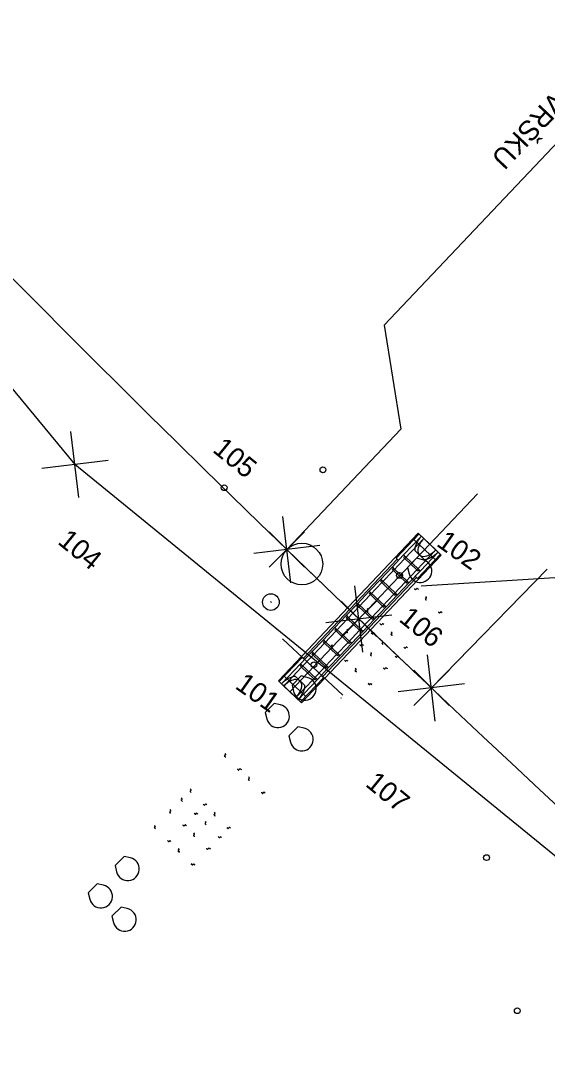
# Model space of a CAD drawing. Extents: x -505028 to -503155, y -1080361 to -1077947.
# Drawn here: x -504027.8 to -503996.3, y -1079378.2 to -1079315.9 of the extents above; entities that cross this region are included whole.
import ezdxf

# ---------------------------------------------------------------- set-up
doc = ezdxf.new("R2010")
doc.units = 0
for name, color, linetype in [('12_vytyceni', 7, 'Continuous'), ('bublinySOPS', 7, 'Continuous'), ('C3D-BOD', 7, 'Continuous'), ('C3D_Povrch - Popis', 7, 'Continuous'), ('C3D_Trasa-Popisy trasy', 7, 'Continuous'), ('Default', 7, 'Continuous'), ('Návěst místo trati_1', 7, 'Continuous'), ('SO021701 popisky', 7, 'Continuous'), ('SO02_tlustá plná', 7, 'Continuous'), ('SO02_tlustá čárkovaná', 7, 'Continuous'), ('SO02_čerchovaná', 7, 'Continuous'), ('Trasa-Geometrie', 7, 'Continuous'), ('Vrstva 17', 7, 'Continuous'), ('Vrstva 24', 7, 'Continuous'), ('Vrstva 7', 7, 'Continuous'), ('ŽKN stavba druh', 7, 'Continuous')]:
    doc.layers.add(name, color=color, linetype=linetype)

# ---------------------------------------------------------------- blocks, each defined once
blk = doc.blocks.new('C045')
at = {"layer": 'ŽKN stavba druh'}
blk.add_circle((0.01, 0), 1.75, dxfattribs=at)
blk = doc.blocks.new('_U7')
at = {"layer": 'Default'}
for p, q in [((8.82, 33.01), (8.6, 33.8)), ((9.85, 32.88), (8.96, 32.9)), ((38.34, 33.8), (38.41, 33.04)), ((46, 33.14), (46, 33.8)), ((46.86, 32.97), (46.14, 32.99)), ((47, 31.9), (47, 32.82)), ((55.82, 33.01), (55.6, 33.8)), ((56.85, 32.88), (55.96, 32.9)), ((69.14, 32.99), (69.86, 32.97)), ((69.86, 32.97), (69.14, 32.99)), ((160.36, 33.01), (160.14, 33.8)), ((161.39, 32.88), (160.5, 32.9)), ((189.88, 33.8), (189.94, 33.04)), ((197.54, 33.14), (197.54, 33.8)), ((198.39, 32.97), (197.68, 32.99)), ((198.54, 31.9), (198.54, 32.82)), ((207.36, 33.01), (207.14, 33.8)), ((208.39, 32.88), (207.5, 32.9)), ((220.68, 32.99), (221.39, 32.97)), ((221.39, 32.97), (220.68, 32.99)), ((8.82, 20.79), (8.6, 20)), ((9.85, 20.92), (8.96, 20.9)), ((38.34, 20), (38.41, 20.76)), ((46, 20.66), (46, 20)), ((46.86, 20.83), (46.14, 20.81)), ((47, 21.9), (47, 20.98)), ((55.82, 20.79), (55.6, 20)), ((56.85, 20.92), (55.96, 20.9)), ((69.14, 20.81), (69.86, 20.83)), ((69.86, 20.83), (69.14, 20.81)), ((125.77, 20), (127.79, 23.3)), ((160.36, 20.79), (160.14, 20)), ((161.39, 20.92), (160.5, 20.9)), ((189.88, 20), (189.94, 20.76)), ((197.54, 20.66), (197.54, 20)), ((198.39, 20.83), (197.68, 20.81)), ((198.54, 21.9), (198.54, 20.98)), ((207.36, 20.79), (207.14, 20)), ((208.39, 20.92), (207.5, 20.9)), ((220.68, 20.81), (221.39, 20.83)), ((221.39, 20.83), (220.68, 20.81)), ((277.31, 20), (279.32, 23.3)), ((8.82, 13.01), (8.6, 13.8)), ((9.85, 12.88), (8.96, 12.9)), ((46, 13.14), (46, 13.8)), ((46.86, 12.97), (46.14, 12.99)), ((47, 11.9), (47, 12.82)), ((55.82, 13.01), (55.6, 13.8)), ((56.85, 12.88), (55.96, 12.9)), ((69.14, 12.99), (69.86, 12.97)), ((69.86, 12.97), (69.14, 12.99)), ((160.36, 13.01), (160.14, 13.8)), ((161.39, 12.88), (160.5, 12.9)), ((197.54, 13.14), (197.54, 13.8)), ((198.39, 12.97), (197.68, 12.99)), ((198.54, 11.9), (198.54, 12.82)), ((207.36, 13.01), (207.14, 13.8)), ((208.39, 12.88), (207.5, 12.9)), ((220.68, 12.99), (221.39, 12.97)), ((221.39, 12.97), (220.68, 12.99)), ((-15.62, 6.63), (-0.12, 6.9)), ((-15.62, 6.63), (-15.58, 4.73)), ((-0.12, 6.9), (9.88, 7.07)), ((9.88, 7.07), (19.88, 7.25)), ((19.88, 7.25), (29.88, 7.42)), ((20.1, -5.6), (19.89, 6.3)), ((29.88, 7.42), (39.87, 7.6)), ((30.1, -5.43), (29.89, 6.47)), ((39.87, 7.6), (49.87, 7.77)), ((40.1, -5.25), (39.89, 6.65)), ((49.87, 7.77), (59.87, 7.95)), ((50.1, -5.08), (49.89, 6.82)), ((59.87, 7.95), (69.87, 8.12)), ((60.09, -4.9), (59.89, 7)), ((60.9, 6.06), (70.9, 6.24)), ((69.87, 8.12), (79.87, 8.3)), ((70.09, -4.73), (69.89, 7.17)), ((70.9, 6.24), (80.9, 6.41)), ((71.08, -3.76), (70.9, 6.24)), ((79.87, 8.3), (89.87, 8.47)), ((80.1, -4.84), (79.88, 7.35)), ((80.9, 6.41), (90.9, 6.59)), ((81.07, -3.59), (80.9, 6.41)), ((89.87, 8.47), (106.36, 8.76)), ((90.09, -4.38), (89.88, 7.52)), ((90.9, 6.59), (106.4, 6.86)), ((91.07, -3.41), (90.9, 6.59)), ((106.4, 6.86), (106.36, 8.76)), ((106.57, -3.14), (106.4, 6.86)), ((-15.58, 4.73), (0.91, 5.02)), ((-15.41, -5.27), (-15.58, 4.73)), ((-6.57, 3.78), (-6.43, -4.01)), ((-1, 0), (-1, 0)), ((-1, 0), (-1, 0)), ((0.1, -5.95), (-0.1, 5.95)), ((-0.02, 1), (-0.02, 1)), ((-0.02, 1), (-0.02, 1)), ((-0.02, 1), (-0.02, 1)), ((-0.02, 1), (-0.02, 1)), ((-0.02, 1), (-0.02, 1)), ((-0.02, 1), (-0.02, 1)), ((-0.02, 1), (-0.02, 1)), ((0.91, 5.02), (10.91, 5.19)), ((1.09, -4.98), (0.91, 5.02)), ((1, 0), (1, 0)), ((1, 0), (1, 0)), ((3.87, 0), (5.89, 3.3)), ((3.87, 0), (5.89, 3.3)), ((8.82, 0.79), (8.6, 0)), ((9.85, 0.92), (8.96, 0.9)), ((10.1, -5.77), (9.89, 6.12)), ((10.91, 5.19), (20.91, 5.37)), ((11.09, -4.81), (10.91, 5.19)), ((20.91, 5.37), (30.91, 5.54)), ((21.08, -4.63), (20.91, 5.37)), ((30.91, 5.54), (40.91, 5.71)), ((31.08, -4.46), (30.91, 5.54)), ((40.91, 5.71), (50.9, 5.89)), ((41.08, -4.28), (40.91, 5.71)), ((46, 0.66), (46, 0)), ((46.86, 0.83), (46.14, 0.81)), ((47, 1.9), (47, 0.98)), ((50.9, 5.89), (60.9, 6.06)), ((51.08, -4.11), (50.9, 5.89)), ((55.82, 0.79), (55.6, 0)), ((56.85, 0.92), (55.96, 0.9)), ((61.08, -3.93), (60.9, 6.06)), ((69.14, 0.81), (69.86, 0.83)), ((69.86, 0.83), (69.14, 0.81)), ((97.42, 5.59), (97.55, -2.19)), ((102.77, 0), (104.79, 3.3)), ((125.77, 0), (127.79, 3.3)), ((160.36, 0.79), (160.14, 0)), ((161.39, 0.92), (160.5, 0.9)), ((197.54, 0.66), (197.54, 0)), ((198.39, 0.83), (197.68, 0.81)), ((198.54, 1.9), (198.54, 0.98)), ((207.36, 0.79), (207.14, 0)), ((208.39, 0.92), (207.5, 0.9)), ((220.68, 0.81), (221.39, 0.83)), ((221.39, 0.83), (220.68, 0.81)), ((254.31, 0), (256.32, 3.3)), ((277.31, 0), (279.32, 3.3)), ((-15.41, -5.27), (1.09, -4.98)), ((-15.38, -7.17), (-15.41, -5.27)), ((1.09, -4.98), (11.09, -4.81)), ((11.09, -4.81), (21.08, -4.63)), ((21.08, -4.63), (31.08, -4.46)), ((30.12, -6.38), (40.11, -6.2)), ((31.08, -4.46), (41.08, -4.28)), ((40.11, -6.2), (50.11, -6.03)), ((41.08, -4.28), (51.08, -4.11)), ((50.11, -6.03), (60.11, -5.85)), ((51.08, -4.11), (61.08, -3.93)), ((60.11, -5.85), (70.11, -5.68)), ((61.08, -3.93), (71.08, -3.76)), ((70.11, -5.68), (80.11, -5.5)), ((71.08, -3.76), (81.07, -3.59)), ((80.11, -5.5), (90.11, -5.33)), ((81.07, -3.59), (91.07, -3.41)), ((90.11, -5.33), (106.6, -5.04)), ((91.07, -3.41), (106.57, -3.14)), ((106.6, -5.04), (106.57, -3.14)), ((-15.38, -7.17), (0.12, -6.9)), ((0.12, -6.9), (10.12, -6.72)), ((10.12, -6.72), (20.12, -6.55)), ((20.12, -6.55), (30.12, -6.38))]:
    blk.add_line(p, q, dxfattribs=at)
for points in [[(9.9, 31.9), (10, 32), (10, 32.73)], [(38.55, 32.9), (39.3, 32.88), (39.39, 32.85)], [(39.5, 32.71), (39.5, 32), (39.4, 31.9)], [(56.9, 31.9), (57, 32), (57, 32.73)], [(69, 33.14), (69, 33.8), (69, 33.14)], [(70, 32.82), (70, 31.9), (70, 32.82)], [(161.44, 31.9), (161.54, 32), (161.54, 32.73)], [(190.09, 32.9), (190.84, 32.88), (190.92, 32.85)], [(191.04, 32.71), (191.04, 32), (190.94, 31.9)], [(208.44, 31.9), (208.54, 32), (208.54, 32.73)], [(220.54, 33.14), (220.54, 33.8), (220.54, 33.14)], [(221.54, 32.82), (221.54, 31.9), (221.54, 32.82)], [(9.9, 21.9), (10, 21.8), (10, 21.07)], [(38.55, 20.9), (39.3, 20.92), (39.39, 20.95)], [(39.5, 21.09), (39.5, 21.8), (39.4, 21.9)], [(56.9, 21.9), (57, 21.8), (57, 21.07)], [(69, 20.66), (69, 20), (69, 20.66)], [(70, 20.98), (70, 21.9), (70, 20.98)], [(116.01, 23.3), (118.03, 20), (125.77, 20)], [(161.44, 21.9), (161.54, 21.8), (161.54, 21.07)], [(190.09, 20.9), (190.84, 20.92), (190.92, 20.95)], [(191.04, 21.09), (191.04, 21.8), (190.94, 21.9)], [(208.44, 21.9), (208.54, 21.8), (208.54, 21.07)], [(220.54, 20.66), (220.54, 20), (220.54, 20.66)], [(221.54, 20.98), (221.54, 21.9), (221.54, 20.98)], [(267.55, 23.3), (269.57, 20), (277.31, 20)], [(9.9, 11.9), (10, 12), (10, 12.73)], [(38.34, 13.8), (38.34, 13.8), (38.41, 13.04)], [(38.55, 12.9), (39.3, 12.88), (39.39, 12.85)], [(39.5, 12.71), (39.5, 12), (39.4, 11.9)], [(56.9, 11.9), (57, 12), (57, 12.73)], [(69, 13.14), (69, 13.8), (69, 13.14)], [(70, 12.82), (70, 11.9), (70, 12.82)], [(161.44, 11.9), (161.54, 12), (161.54, 12.73)], [(189.88, 13.8), (189.88, 13.8), (189.94, 13.04)], [(190.09, 12.9), (190.84, 12.88), (190.92, 12.85)], [(191.04, 12.71), (191.04, 12), (190.94, 11.9)], [(208.44, 11.9), (208.54, 12), (208.54, 12.73)], [(220.54, 13.14), (220.54, 13.8), (220.54, 13.14)], [(221.54, 12.82), (221.54, 11.9), (221.54, 12.82)], [(0.91, 5.02), (0.9, 5.97), (-0.1, 5.95), (-0.12, 6.9)], [(10.91, 5.19), (10.89, 6.14), (9.89, 6.12), (9.88, 7.07)], [(20.91, 5.37), (20.89, 6.32), (19.89, 6.3), (19.88, 7.25)], [(30.91, 5.54), (30.89, 6.49), (29.89, 6.47), (29.88, 7.42)], [(40.91, 5.71), (40.89, 6.66), (39.89, 6.65), (39.87, 7.6)], [(50.9, 5.89), (50.89, 6.84), (49.89, 6.82), (49.87, 7.77)], [(60.9, 6.06), (60.89, 7.01), (59.89, 7), (59.87, 7.95)], [(70.9, 6.24), (70.89, 7.19), (69.89, 7.17), (69.87, 8.12)], [(80.9, 6.41), (80.88, 7.36), (79.88, 7.35), (79.87, 8.3)], [(90.9, 6.59), (90.88, 7.54), (89.88, 7.52), (89.87, 8.47)], [(-5.89, 3.3), (-3.87, 0), (3.87, 0)], [(-5.89, 3.3), (-3.87, 0), (3.87, 0)], [(-1, 0), (-1, 0), (-1, 0)], [(-1, 0), (-1, 0), (-1, 0)], [(1, 0), (1, 0), (1, 0)], [(1, 0), (1, 0), (1, 0)], [(9.9, 1.9), (10, 1.8), (10, 1.07)], [(38.34, 0), (38.34, 0), (38.41, 0.76)], [(38.55, 0.9), (39.3, 0.92), (39.39, 0.95)], [(39.5, 1.09), (39.5, 1.8), (39.4, 1.9)], [(56.9, 1.9), (57, 1.8), (57, 1.07)], [(69, 0.66), (69, 0), (69, 0.66)], [(70, 0.98), (70, 1.9), (70, 0.98)], [(93.01, 3.3), (95.03, 0), (102.77, 0)], [(116.01, 3.3), (118.03, 0), (125.77, 0)], [(161.44, 1.9), (161.54, 1.8), (161.54, 1.07)], [(189.88, 0), (189.88, 0), (189.94, 0.76)], [(190.09, 0.9), (190.84, 0.92), (190.92, 0.95)], [(191.04, 1.09), (191.04, 1.8), (190.94, 1.9)], [(208.44, 1.9), (208.54, 1.8), (208.54, 1.07)], [(220.54, 0.66), (220.54, 0), (220.54, 0.66)], [(221.54, 0.98), (221.54, 1.9), (221.54, 0.98)], [(244.55, 3.3), (246.57, 0), (254.31, 0)], [(267.55, 3.3), (269.57, 0), (277.31, 0)], [(1.09, -4.98), (1.1, -5.93), (0.1, -5.95), (0.12, -6.9)], [(11.09, -4.81), (11.1, -5.76), (10.1, -5.77), (10.12, -6.72)], [(21.08, -4.63), (21.1, -5.58), (20.1, -5.6), (20.12, -6.55)], [(31.08, -4.46), (31.1, -5.41), (30.1, -5.43), (30.12, -6.38)], [(41.08, -4.28), (41.09, -5.23), (40.1, -5.25), (40.11, -6.2)], [(51.08, -4.11), (51.09, -5.06), (50.1, -5.08), (50.11, -6.03)], [(61.08, -3.93), (61.09, -4.88), (60.09, -4.9), (60.11, -5.85)], [(71.08, -3.76), (71.09, -4.71), (70.09, -4.73), (70.11, -5.68)], [(81.07, -3.59), (81.09, -4.54), (80.09, -4.55), (80.11, -5.5)], [(91.07, -3.41), (91.09, -4.36), (90.09, -4.38), (90.11, -5.33)]]:
    blk.add_lwpolyline(points, dxfattribs=at)
for centre, radius, start, end in [((8.97, 33.05), 0.15, 195.39219, 268.50567), ((9.85, 32.73), 0.15, 0, 88.50567), ((38.56, 33.05), 0.15, 185, 268.03686), ((39.35, 32.71), 0.15, 0, 75), ((46.15, 33.14), 0.15, 180, 268), ((46.85, 32.82), 0.15, 360, 88), ((55.97, 33.05), 0.15, 195.39219, 268.50567), ((56.85, 32.73), 0.15, 0, 88.50567), ((69.15, 33.14), 0.15, 180, 268), ((69.15, 33.14), 0.15, 180, 268), ((69.85, 32.82), 0.15, 360, 88), ((69.85, 32.82), 0.15, 360, 88), ((121.9, 26.9), 6.9, 328.57348, 211.42652), ((160.5, 33.05), 0.15, 195.39219, 268.50567), ((161.39, 32.73), 0.15, 0, 88.50567), ((190.09, 33.05), 0.15, 185, 268.03686), ((190.89, 32.71), 0.15, 0, 75), ((197.69, 33.14), 0.15, 180, 268), ((198.39, 32.82), 0.15, 360, 88), ((207.5, 33.05), 0.15, 195.39219, 268.50567), ((208.39, 32.73), 0.15, 0, 88.50567), ((220.69, 33.14), 0.15, 180, 268), ((220.69, 33.14), 0.15, 180, 268), ((221.39, 32.82), 0.15, 0, 88), ((221.39, 32.82), 0.15, 360, 88), ((273.44, 26.9), 6.9, 328.57348, 211.42652), ((8.97, 20.75), 0.15, 91.49433, 164.60781), ((9.85, 21.07), 0.15, 271.49433, 360), ((38.56, 20.75), 0.15, 91.96314, 175), ((39.35, 21.09), 0.15, 285, 360), ((46.15, 20.66), 0.15, 92, 180), ((46.85, 20.98), 0.15, 272, 360), ((55.97, 20.75), 0.15, 91.49433, 164.60781), ((56.85, 21.07), 0.15, 271.49433, 360), ((69.15, 20.66), 0.15, 92, 180), ((69.15, 20.66), 0.15, 92, 180), ((69.85, 20.98), 0.15, 272, 0), ((69.85, 20.98), 0.15, 272, 360), ((160.5, 20.75), 0.15, 91.49433, 164.60781), ((161.39, 21.07), 0.15, 271.49433, 360), ((190.09, 20.75), 0.15, 91.96314, 175), ((190.89, 21.09), 0.15, 285, 360), ((197.69, 20.66), 0.15, 92, 180), ((198.39, 20.98), 0.15, 272, 360), ((207.5, 20.75), 0.15, 91.49433, 164.60781), ((208.39, 21.07), 0.15, 271.49433, 360), ((220.69, 20.66), 0.15, 92, 180), ((220.69, 20.66), 0.15, 92, 180), ((221.39, 20.98), 0.15, 272, 360), ((221.39, 20.98), 0.15, 272, 360), ((0, 6.9), 6.9, 328.57348, 211.42652), ((0, 6.9), 6.9, 328.57348, 211.42652), ((8.97, 13.05), 0.15, 195.39219, 268.50567), ((9.85, 12.73), 0.15, 0, 88.50567), ((38.56, 13.05), 0.15, 185, 268.03686), ((39.35, 12.71), 0.15, 360, 75), ((46.15, 13.14), 0.15, 180, 268), ((46.85, 12.82), 0.15, 0, 88), ((55.97, 13.05), 0.15, 195.39219, 268.50567), ((56.85, 12.73), 0.15, 360, 88.50567), ((69.15, 13.14), 0.15, 180, 268), ((69.15, 13.14), 0.15, 180, 268), ((69.85, 12.82), 0.15, 0, 88), ((69.85, 12.82), 0.15, 0, 88), ((98.9, 6.9), 6.9, 328.57348, 211.42652), ((121.9, 6.9), 6.9, 328.57348, 211.42652), ((160.5, 13.05), 0.15, 195.39219, 268.50567), ((161.39, 12.73), 0.15, 0, 88.50567), ((190.09, 13.05), 0.15, 185, 268.03686), ((190.89, 12.71), 0.15, 360, 75), ((197.69, 13.14), 0.15, 180, 268), ((198.39, 12.82), 0.15, 0, 88), ((207.5, 13.05), 0.15, 195.39219, 268.50567), ((208.39, 12.73), 0.15, 0, 88.50567), ((220.69, 13.14), 0.15, 180, 268), ((220.69, 13.14), 0.15, 180, 268), ((221.39, 12.82), 0.15, 0, 88), ((221.39, 12.82), 0.15, 0, 88), ((250.44, 6.9), 6.9, 328.57348, 211.42652), ((273.44, 6.9), 6.9, 328.57348, 211.42652), ((-1, 0), 0.00069, 328.57348, 211.42652), ((-1, 0), 0.00069, 328.57348, 211.42652), ((1, 0), 0.00069, 328.57348, 211.42652), ((1, 0), 0.00069, 328.57348, 211.42652), ((8.97, 0.75), 0.15, 91.49433, 164.60781), ((9.85, 1.07), 0.15, 271.49433, 360), ((38.56, 0.75), 0.15, 91.96314, 175), ((39.35, 1.09), 0.15, 285, 0), ((46.15, 0.66), 0.15, 92, 180), ((46.85, 0.98), 0.15, 272, 0), ((55.97, 0.75), 0.15, 91.49433, 164.60781), ((56.85, 1.07), 0.15, 271.49433, 0), ((69.15, 0.66), 0.15, 92, 180), ((69.15, 0.66), 0.15, 92, 180), ((69.85, 0.98), 0.15, 272, 0), ((69.85, 0.98), 0.15, 272, 0), ((160.5, 0.75), 0.15, 91.49433, 164.60781), ((161.39, 1.07), 0.15, 271.49433, 360), ((190.09, 0.75), 0.15, 91.96314, 175), ((190.89, 1.09), 0.15, 285, 0), ((197.69, 0.66), 0.15, 92, 180), ((198.39, 0.98), 0.15, 272, 0), ((207.5, 0.75), 0.15, 91.49433, 164.60781), ((208.39, 1.07), 0.15, 271.49433, 360), ((220.69, 0.66), 0.15, 92, 180), ((220.69, 0.66), 0.15, 92, 180), ((221.39, 0.98), 0.15, 272, 360), ((221.39, 0.98), 0.15, 272, 0)]:
    blk.add_arc(centre, radius, start, end, dxfattribs=at)
for centre, major_axis, ratio, start_param, end_param in [((-15.5, -0.27), (10.9, 0.19), 0.633028, 0.599375, 1.570796), ((106.48, 1.86), (-10.9, -0.19), 0.633028, 4.712389, 5.68381), ((106.48, 1.86), (-9, -0.16), 0.555556, 4.712389, 7.853982), ((-15.5, -0.27), (9, 0.16), 0.555556, 4.712389, 7.853982), ((-15.5, -0.27), (10.9, 0.19), 0.633028, 4.712389, 5.68381), ((106.48, 1.86), (-10.9, -0.19), 0.633028, 0.599375, 1.570796)]:
    blk.add_ellipse(centre, major_axis=major_axis, ratio=ratio, start_param=start_param, end_param=end_param, dxfattribs=at)
blk = doc.blocks.new('Vytyc_bod')
at = {"layer": 'Default'}
blk.add_circle((0, 0), 0.01, dxfattribs=at)
blk = doc.blocks.new('C093_5')
at = {"layer": 'Návěst místo trati_1'}
blk.add_line((-0.5, 0), (0.5, 0), dxfattribs=at)
blk.add_circle((0, 0), 5, dxfattribs=at)
blk = doc.blocks.new('_kolecko-HB')
at = {"layer": 'Default'}
blk.add_circle((0, 0.02), 5, dxfattribs=at)
blk = doc.blocks.new('_U969')
at = {"layer": 'Default'}
for p, q in [((-7.07, -7.07), (7.07, 7.07)), ((-7.07, 7.07), (7.07, -7.07))]:
    blk.add_line(p, q, dxfattribs=at)

msp = doc.modelspace()

# ---------------------------------------------------------------- linework, layer by layer
at = {"layer": 'bublinySOPS'}
msp.add_line((-504003.825, -1079349.785), (-503959.085, -1079347.009), dxfattribs=at)
at = {"layer": 'C3D-BOD'}
for p, q in [((-504012.949, -1079348.673), (-504010.827, -1079346.552)), ((-504012.949, -1079346.552), (-504010.827, -1079348.673)), ((-504008.626, -1079352.834), (-504006.504, -1079350.712)), ((-504008.626, -1079350.712), (-504006.504, -1079352.834)), ((-504004.278, -1079356.971), (-504002.156, -1079354.85)), ((-504004.278, -1079354.85), (-504002.156, -1079356.971))]:
    msp.add_line(p, q, dxfattribs=at)
at = {"layer": 'Default'}
for p, q in [((-504138.016, -1079205.621), (-504024.593, -1079342.511)), ((-503974.71, -1079301.011), (-504006.043, -1079334.152)), ((-504006.043, -1079334.152), (-504005.05, -1079340.38)), ((-504005.05, -1079340.38), (-504011.888, -1079347.613)), ((-503874.079, -1079465.25), (-504024.593, -1079342.511)), ((-503996.272, -1079348.781), (-504003.217, -1079355.911))]:
    msp.add_line(p, q, dxfattribs=at)
for centre, radius in [((-504012.289, -1079353.101), 0.00355), ((-504008.628, -1079356.513), 0.0036)]:
    msp.add_circle(centre, radius, dxfattribs=at)
msp.add_arc((-503267.771, -1078578.724), 1070, 225.938013, 226.580584, dxfattribs=at)
at = {"layer": 'SO02_tlustá plná'}
for p, q in [((-504010.828, -1079354.215), (-504010.973, -1079354.078)), ((-504009.681, -1079355.302), (-504009.826, -1079355.164))]:
    msp.add_line(p, q, dxfattribs=at)
at = {"layer": 'SO02_tlustá čárkovaná'}
for p, q in [((-504012.392, -1079355.488), (-504004.003, -1079346.631)), ((-504004.003, -1079346.631), (-504002.623, -1079347.937)), ((-504003.959, -1079346.672), (-504005.335, -1079348.124)), ((-504002.976, -1079348.223), (-504004.269, -1079346.999)), ((-504002.623, -1079347.937), (-504011.013, -1079356.795)), ((-504010.908, -1079354.14), (-504005.269, -1079348.186)), ((-504005.335, -1079348.124), (-504005.189, -1079348.262)), ((-504002.667, -1079347.896), (-504004.042, -1079349.348)), ((-504004.108, -1079349.286), (-504009.746, -1079355.24)), ((-504004.042, -1079349.348), (-504004.187, -1079349.211)), ((-504012.349, -1079355.53), (-504010.973, -1079354.078)), ((-504010.747, -1079356.427), (-504012.039, -1079355.203)), ((-504011.056, -1079356.754), (-504009.681, -1079355.302)), ((-504012.392, -1079355.488), (-504011.013, -1079356.795))]:
    msp.add_line(p, q, dxfattribs=at)
at = {"layer": 'SO02_čerchovaná'}
msp.add_line((-504011.702, -1079356.142), (-504000.452, -1079344.263), dxfattribs=at)
at = {"layer": 'Trasa-Geometrie'}
msp.add_arc((-503267.771, -1078578.724), 1070, 220.848965, 228.795915, dxfattribs=at)
at = {"layer": 'Vrstva 17'}
msp.add_line((-504012.153, -1079352.971), (-504008.52, -1079356.338), dxfattribs=at)
msp.add_line((-504012.153, -1079352.971), (-504008.52, -1079356.338), dxfattribs=at)

# ---------------------------------------------------------------- block references
at = {"layer": '12_vytyceni', "xscale": 9.999999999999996e-05, "yscale": 9.999999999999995e-05, "rotation": -43.444252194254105}
for p in [(-504003.313, -1079347.284), (-504011.702, -1079356.142)]:
    msp.add_blockref('Vytyc_bod', p, dxfattribs=at)
at = {"layer": 'C3D-BOD', "xscale": 0.19999999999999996, "yscale": 0.1999999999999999, "rotation": 141.804}
for p in [(-504024.593, -1079342.511), (-504011.888, -1079347.613), (-504007.565, -1079351.773), (-504003.218, -1079355.909)]:
    msp.add_blockref('_U969', p, dxfattribs=at)
at = {"layer": 'C3D_Trasa-Popisy trasy', "xscale": 0.25, "yscale": 0.25, "rotation": -43.99479017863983}
msp.add_blockref('_kolecko-HB', (-504010.986, -1079348.485), dxfattribs=at)
at = {"layer": 'SO02_tlustá plná', "xscale": 0.09999999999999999, "yscale": 0.10000000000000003, "rotation": -134.44425218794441}
msp.add_blockref('_U7', (-504004.379, -1079348.409), dxfattribs=at)
at = {"layer": 'Vrstva 24', "xscale": 0.1, "yscale": 0.10000000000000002}
for p in [(-504009.72, -1079342.825), (-504009.72, -1079342.825), (-504009.72, -1079342.825), (-504009.72, -1079342.825), (-504015.64, -1079343.902), (-504015.64, -1079343.902), (-504015.64, -1079343.902), (-504015.64, -1079343.902), (-504005.127, -1079349.158), (-504005.127, -1079349.158), (-504005.127, -1079349.158), (-504005.127, -1079349.158), (-504010.266, -1079354.53), (-504010.266, -1079354.53), (-504010.266, -1079354.53), (-504010.266, -1079354.53), (-503999.911, -1079366.089), (-503999.911, -1079366.089), (-503998.069, -1079375.273), (-503998.069, -1079375.273), (-503998.069, -1079375.273), (-503998.069, -1079375.273)]:
    msp.add_blockref('C045', p, dxfattribs=at)
at = {"layer": 'Vrstva 7', "xscale": 0.09999999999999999, "yscale": 0.09999999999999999, "rotation": -47.2268619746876}
msp.add_blockref('C093_5', (-504012.84, -1079350.758), dxfattribs=at)
msp.add_blockref('C093_5', (-504012.84, -1079350.758), dxfattribs=at)

# ---------------------------------------------------------------- texts
at = {"layer": '12_vytyceni'}
for s, p in [('102', (-504002.976, -1079347.349)), ('101', (-504015.051, -1079355.894))]:
    msp.add_text(s, height=1.2, rotation=324.55346, dxfattribs=at).set_placement(p)
at = {"layer": 'C3D_Povrch - Popis'}
for s, p in [('105', (-504016.394, -1079341.711)), ('104', (-504025.686, -1079347.22)), ('106', (-504005.223, -1079351.866)), ('107', (-504007.233, -1079361.756))]:
    msp.add_text(s, height=1.2, rotation=320.804, dxfattribs=at).set_placement(p)
at = {"layer": 'SO021701 popisky'}
msp.add_text('REKONSTRUKCE ŽEL.SVRŠKU', height=1.2, rotation=226.56496, dxfattribs=at).set_placement((-503983.327, -1079306.779))

doc.saveas('drawing.dxf')
